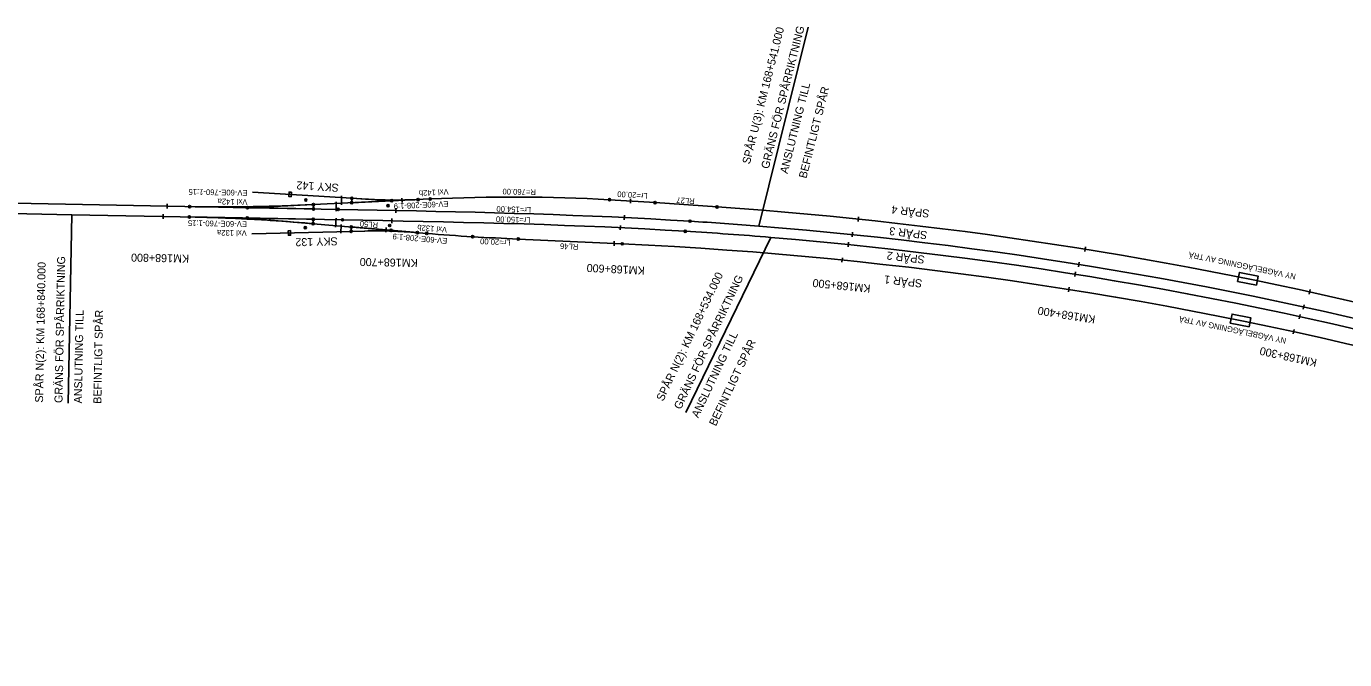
# Model space of a CAD drawing. Extents: x 185262 to 188870, y 6548921 to 6550022.
# Drawn here: x 186420 to 186997, y 6549712 to 6549989 of the extents above; entities that cross this region are included whole.
import ezdxf

# ---------------------------------------------------------------- set-up
doc = ezdxf.new("R2010")
doc.units = 0
for name, color, linetype in [('Befintligt spår som justeras', 7, 'Continuous'), ('BKS 1 verklig mangan P', 7, 'Continuous'), ('BKS 2 verklig mangan P', 7, 'Continuous'), ('FSK P', 7, 'Continuous'), ('Gräns för anslutning L', 7, 'Continuous'), ('Gräns för anslutning T', 7, 'Continuous'), ('Hinderpåle P', 7, 'Continuous'), ('Längdm markering (primär) L', 7, 'Continuous'), ('Längdmätning T', 7, 'Continuous'), ('MKP fiktiv P', 7, 'Continuous'), ('Ny Vägbeläggning L', 7, 'Continuous'), ('Ny Vägbeläggning T', 7, 'Continuous'), ('Spår bef projekterat behålls L', 7, 'Continuous'), ('Spår nr T', 7, 'Continuous'), ('Spårgeometri T', 7, 'Continuous'), ('Spårmitt projekterad L', 7, 'Continuous'), ('Spårmitt tp P', 7, 'Continuous'), ('Stoppbock P', 7, 'Continuous'), ('Växel linjevikt 2 L', 7, 'Continuous'), ('Växelnummer T', 7, 'Continuous'), ('Växeltyp T', 7, 'Continuous')]:
    doc.layers.add(name, color=color, linetype=linetype)

msp = doc.modelspace()

# ---------------------------------------------------------------- linework, layer by layer
at = {"layer": 'Befintligt spår som justeras'}
for p, q in [((186556.53, 6549908.61), (186401.75, 6549911.55)), ((186558.43, 6549904.05), (186440.01, 6549906.29))]:
    msp.add_line(p, q, dxfattribs=at)
for points in [[(186710.43, 6549903.46), (186701.89, 6549903.97), (186693.34, 6549904.45), (186684.8, 6549904.89), (186676.25, 6549905.29), (186667.71, 6549905.66), (186659.16, 6549906), (186650.61, 6549906.32), (186642.06, 6549906.6), (186633.51, 6549906.87), (186624.95, 6549907.12), (186616.4, 6549907.34), (186607.85, 6549907.55), (186599.3, 6549907.75), (186590.74, 6549907.94), (186582.19, 6549908.11), (186573.63, 6549908.28), (186565.08, 6549908.45), (186556.53, 6549908.61)], [(186708.34, 6549899.08), (186699.53, 6549899.6), (186690.72, 6549900.08), (186681.91, 6549900.52), (186673.09, 6549900.92), (186664.28, 6549901.29), (186655.46, 6549901.63), (186646.64, 6549901.94), (186637.82, 6549902.23), (186629, 6549902.49), (186620.18, 6549902.73), (186611.36, 6549902.95), (186602.54, 6549903.16), (186593.72, 6549903.35), (186584.9, 6549903.53), (186576.08, 6549903.71), (186567.25, 6549903.88), (186558.43, 6549904.05)]]:
    msp.add_lwpolyline(points, dxfattribs=at)
for centre, radius, start, end in [((186599.87, 6548133.91), 1773, 85.4491, 86.42498), ((186599.86, 6548133.91), 1768.5, 85.26658, 86.48344)]:
    msp.add_arc(centre, radius, start, end, dxfattribs=at)
at = {"layer": 'BKS 1 verklig mangan P'}
for centre in [(186562.49, 6549911.54), (186545.74, 6549908.81), (186545.65, 6549904.29), (186562.29, 6549900.93)]:
    msp.add_circle(centre, 0.5, dxfattribs=at)
at = {"layer": 'BKS 2 verklig mangan P'}
for centre in [(186545.71, 6549910.74), (186562.51, 6549913.47), (186545.55, 6549902.37), (186562.23, 6549899)]:
    msp.add_circle(centre, 0.5, dxfattribs=at)
at = {"layer": 'FSK P'}
for centre in [(186591.48, 6549912.92), (186491.45, 6549905.32), (186491.53, 6549909.84), (186591.2, 6549898.45)]:
    msp.add_circle(centre, 0.5, dxfattribs=at)
at = {"layer": 'Gräns för anslutning L'}
for p, q in [((186740.55, 6549901.32), (186762.12, 6549988.27)), ((186440.01, 6549906.29), (186438.45, 6549823.88)), ((186745.8, 6549896.38), (186708.64, 6549819.85))]:
    msp.add_line(p, q, dxfattribs=at)
at = {"layer": 'Hinderpåle P'}
for centre, radius in [((186542.39, 6549912.66), 0.5), ((186542.39, 6549912.66), 0.2), ((186578.39, 6549910.24), 0.5), ((186578.39, 6549910.24), 0.2), ((186542.16, 6549900.57), 0.5), ((186542.16, 6549900.57), 0.2), ((186579.07, 6549901.58), 0.5), ((186579.07, 6549901.58), 0.2)]:
    msp.add_circle(centre, radius, dxfattribs=at)
at = {"layer": 'Längdm markering (primär) L'}
for points in [[(186481.72, 6549909.03), (186481.76, 6549911.03)], [(186584.5, 6549911.58), (186584.4, 6549913.58)], [(186684.32, 6549911.3), (186684.45, 6549913.29)], [(186479.99, 6549904.54), (186480.03, 6549906.54)], [(186581.7, 6549907.12), (186581.74, 6549909.12)], [(186681.62, 6549904.04), (186681.72, 6549906.04)], [(186783.95, 6549903.36), (186784.16, 6549905.35)], [(186577.35, 6549898.64), (186577.52, 6549900.63)], [(186579.97, 6549902.63), (186580.01, 6549904.63)], [(186679.89, 6549899.62), (186679.99, 6549901.61)], [(186677.2, 6549892.72), (186677.3, 6549894.72)], [(186779.55, 6549892.26), (186779.76, 6549894.25)], [(186781.28, 6549896.6), (186781.48, 6549898.59)], [(186883.02, 6549890.23), (186883.34, 6549892.21)], [(186776.87, 6549885.49), (186777.08, 6549887.48)], [(186880.35, 6549883.57), (186880.67, 6549885.55)], [(186878.64, 6549879.29), (186878.95, 6549881.27)], [(186875.97, 6549872.63), (186876.29, 6549874.6)], [(186981.19, 6549871.56), (186981.62, 6549873.52)], [(186978.54, 6549864.98), (186978.97, 6549866.93)], [(186976.83, 6549860.75), (186977.26, 6549862.7)], [(186974.18, 6549854.16), (186974.61, 6549856.11)]]:
    msp.add_lwpolyline(points, dxfattribs=at)
at = {"layer": 'MKP fiktiv P'}
for centre in [(186579.95, 6549912.37), (186516.75, 6549904.84), (186516.83, 6549909.36), (186579.7, 6549899.44)]:
    msp.add_circle(centre, 0.5, dxfattribs=at)
at = {"layer": 'Ny Vägbeläggning L'}
for points in [[(186958.12, 6549875.45), (186949.89, 6549877.12), (186950.68, 6549881.04), (186958.92, 6549879.37)], [(186954.92, 6549857.22), (186946.69, 6549858.9), (186947.49, 6549862.82), (186955.72, 6549861.14)]]:
    msp.add_lwpolyline(points, close=True, dxfattribs=at)
at = {"layer": 'Spår bef projekterat behålls L'}
msp.add_line((186440.01, 6549906.29), (185262.41, 6549928.63), dxfattribs=at)
for centre, radius, start, end in [((186599.87, 6548133.91), 1773, 74.68797, 85.4491), ((186599.86, 6548133.91), 1768.5, 74.0572, 85.26658)]:
    msp.add_arc(centre, radius, start, end, dxfattribs=at)
at = {"layer": 'Spårmitt projekterad L'}
for p, q in [((186562.51, 6549913.47), (186519.07, 6549916.21)), ((186596.76, 6549913.17), (186545.71, 6549910.74)), ((186568.43, 6549913.1), (186562.51, 6549913.47)), ((186722.27, 6549909.7), (186695.16, 6549911.57)), ((186545.71, 6549910.74), (186542.11, 6549910.57)), ((186545.55, 6549902.37), (186541.96, 6549902.68)), ((186595.28, 6549898.1), (186545.55, 6549902.37)), ((186562.23, 6549899), (186518.72, 6549897.91)), ((186568.16, 6549899.15), (186562.23, 6549899)), ((186680.81, 6549893.55), (186635.28, 6549895.65))]:
    msp.add_line(p, q, dxfattribs=at)
for points in [[(186695.16, 6549911.57), (186692.67, 6549911.74), (186690.17, 6549911.91), (186687.68, 6549912.08), (186685.18, 6549912.24), (186682.69, 6549912.4), (186680.19, 6549912.56), (186677.7, 6549912.71), (186675.2, 6549912.85)], [(186635.28, 6549895.65), (186632.78, 6549895.76), (186630.28, 6549895.88), (186627.78, 6549896), (186625.29, 6549896.12), (186622.79, 6549896.24), (186620.29, 6549896.37), (186617.8, 6549896.51), (186615.3, 6549896.65)]]:
    msp.add_lwpolyline(points, dxfattribs=at)
for centre, radius, start, end in [((186581.56, 6550121.12), 208.44, 266.38717, 272.72736), ((186632.92, 6549154.03), 760, 86.81095, 92.72736), ((186477.03, 6549145.45), 760, 85.09921, 88.91329), ((186505.94, 6550669.71), 760, 268.91328, 272.72736), ((186599.87, 6548133.91), 1780, 65.67718, 86.05706), ((186573.4, 6549690.78), 208.44, 85.09921, 91.4394), ((186660.21, 6550655.33), 760, 265.09921, 266.61233), ((186599.86, 6548133.91), 1761.5, 63.60482, 87.36623)]:
    msp.add_arc(centre, radius, start, end, dxfattribs=at)
at = {"layer": 'Spårmitt tp P'}
for centre in [(186596.76, 6549913.17), (186675.2, 6549912.85), (186695.16, 6549911.57), (186556.53, 6549908.61), (186722.27, 6549909.7), (186558.43, 6549904.05), (186708.34, 6549899.08), (186710.43, 6549903.46), (186595.28, 6549898.1), (186615.3, 6549896.65), (186635.28, 6549895.65), (186680.81, 6549893.55)]:
    msp.add_circle(centre, 0.5, dxfattribs=at)
at = {"layer": 'Stoppbock P'}
for points in [[(186535.97, 6549914.14), (186536.1, 6549916.14), (186535.1, 6549916.2), (186534.97, 6549914.21)], [(186535.69, 6549899.33), (186535.74, 6549897.34), (186534.74, 6549897.31), (186534.69, 6549899.31)]]:
    msp.add_lwpolyline(points, close=True, dxfattribs=at)
at = {"layer": 'Växel linjevikt 2 L'}
for points in [[(186555.59, 6549911.93), (186555.65, 6549907.91)], [(186558.02, 6549914.47), (186557.99, 6549910.61)], [(186558.02, 6549914.47), (186557.99, 6549910.61)], [(186591.48, 6549912.92), (186579.95, 6549912.37)], [(186491.45, 6549905.32), (186516.75, 6549904.84)], [(186491.53, 6549909.84), (186516.83, 6549909.36)], [(186555.59, 6549904.82), (186555.38, 6549900.81)], [(186557.71, 6549898.17), (186557.83, 6549902.03)], [(186557.71, 6549898.17), (186557.83, 6549902.03)], [(186591.2, 6549898.45), (186579.7, 6549899.44)]]:
    msp.add_lwpolyline(points, dxfattribs=at)
for points in [[(186579.95, 6549912.37), (186562.49, 6549911.54), (186562.51, 6549913.47)], [(186591.48, 6549912.92), (186562.49, 6549911.54), (186562.51, 6549913.47), (186568.43, 6549913.1), (186568.43, 6549913.1), (186569.78, 6549913.02), (186571.14, 6549912.94), (186572.49, 6549912.88), (186573.85, 6549912.83), (186575.2, 6549912.78), (186576.56, 6549912.74), (186577.92, 6549912.71), (186579.27, 6549912.7), (186580.63, 6549912.68), (186581.99, 6549912.68), (186583.34, 6549912.69), (186584.7, 6549912.71), (186586.05, 6549912.73), (186587.41, 6549912.76), (186588.77, 6549912.81), (186590.12, 6549912.86)], [(186491.45, 6549905.32), (186545.65, 6549904.29), (186545.55, 6549902.37), (186541.96, 6549902.68), (186541.96, 6549902.68), (186539.44, 6549902.89), (186536.92, 6549903.09), (186534.39, 6549903.29), (186531.87, 6549903.47), (186529.35, 6549903.65), (186526.82, 6549903.82), (186524.3, 6549903.98), (186521.78, 6549904.14), (186519.25, 6549904.28), (186516.72, 6549904.42), (186514.2, 6549904.55), (186511.67, 6549904.67), (186509.14, 6549904.78), (186506.62, 6549904.88), (186504.09, 6549904.97), (186501.56, 6549905.06), (186499.03, 6549905.14), (186496.5, 6549905.21), (186493.97, 6549905.27)], [(186491.53, 6549909.84), (186545.74, 6549908.81), (186545.71, 6549910.74), (186542.11, 6549910.57), (186542.11, 6549910.57), (186539.58, 6549910.45), (186537.05, 6549910.34), (186534.53, 6549910.24), (186532, 6549910.15), (186529.47, 6549910.07), (186526.94, 6549910), (186524.41, 6549909.93), (186521.88, 6549909.87), (186519.35, 6549909.82), (186516.83, 6549909.78), (186514.3, 6549909.75), (186511.77, 6549909.73), (186509.24, 6549909.71), (186506.71, 6549909.71), (186504.18, 6549909.71), (186501.65, 6549909.72), (186499.12, 6549909.74), (186496.59, 6549909.76), (186494.06, 6549909.8)], [(186516.83, 6549909.36), (186545.74, 6549908.81), (186545.71, 6549910.74)], [(186516.75, 6549904.84), (186545.65, 6549904.29), (186545.55, 6549902.37)], [(186579.7, 6549899.44), (186562.29, 6549900.93), (186562.23, 6549899)], [(186591.2, 6549898.45), (186562.29, 6549900.93), (186562.23, 6549899), (186568.16, 6549899.15), (186568.16, 6549899.15), (186569.52, 6549899.18), (186570.87, 6549899.2), (186572.23, 6549899.21), (186573.59, 6549899.22), (186574.94, 6549899.21), (186576.3, 6549899.2), (186577.66, 6549899.17), (186579.01, 6549899.14), (186580.37, 6549899.1), (186581.73, 6549899.05), (186583.08, 6549898.99), (186584.44, 6549898.92), (186585.79, 6549898.85), (186587.15, 6549898.76), (186588.5, 6549898.67), (186589.85, 6549898.57)]]:
    msp.add_lwpolyline(points, close=True, dxfattribs=at)

# ---------------------------------------------------------------- texts
at = {"layer": 'Gräns för anslutning T'}
for s, rotation, p in [('SPÅR U(3): KM 168+541.000', 75.84713, (186736.57, 6549928.17)), ('GRÄNS FÖR SPÅRRIKTNING', 75.84713, (186744.82, 6549926.09)), ('ANSLUTNING TILL ', 75.84713, (186753.06, 6549924.01)), ('BEFINTLIGT SPÅR', 75.84713, (186761.3, 6549921.93)), ('SPÅR N(2): KM 168+840.000', 88.91329, (186427.45, 6549824.09)), ('GRÄNS FÖR SPÅRRIKTNING', 88.91329, (186435.95, 6549823.93)), ('SPÅR N(2): KM 168+534.000', 64.65656, (186698.67, 6549824.5)), ('GRÄNS FÖR SPÅRRIKTNING', 64.65656, (186706.35, 6549820.86)), ('ANSLUTNING TILL ', 88.91329, (186444.45, 6549823.77)), ('BEFINTLIGT SPÅR', 88.91329, (186452.95, 6549823.61)), ('ANSLUTNING TILL ', 64.65656, (186714.03, 6549817.23)), ('BEFINTLIGT SPÅR', 64.65656, (186721.72, 6549813.59))]:
    msp.add_text(s, height=3.5, rotation=rotation, dxfattribs=at).set_placement(p)
at = {"layer": 'Längdmätning T'}
for s, rotation, p in [('KM168+800', 178.91329, (186491.36, 6549888.82)), ('KM168+700', 178.86309, (186591.37, 6549886.9)), ('KM168+600', 177.31751, (186690.66, 6549883.59)), ('KM168+500', 174.16507, (186789.47, 6549875.66)), ('KM168+400', 170.92527, (186887.86, 6549862.12)), ('KM168+300', 167.68548, (186984.82, 6549843.14))]:
    msp.add_text(s, height=3.5, rotation=rotation, dxfattribs=at).set_placement(p)
at = {"layer": 'Ny Vägbeläggning T'}
for p in [(186975.54, 6549880.37), (186971.34, 6549852.32)]:
    msp.add_text('NY VÄGBELÄGGNING AV TRÄ', height=2.5, rotation=168.21567, dxfattribs=at).set_placement(p)
at = {"layer": 'Spår nr T'}
for s, rotation, p in [('SKY 142', 176.38717, (186556.88, 6549919.75)), ('SPÅR 4', 173.34743, (186815.27, 6549908.42)), ('SPÅR 3', 173.31516, (186814.34, 6549899)), ('SKY 132', 181.4394, (186556.26, 6549896.43)), ('SPÅR 2', 173.45469, (186813.2, 6549888.31)), ('SPÅR 1', 173.41767, (186812.11, 6549877.88))]:
    msp.add_text(s, height=3.5, rotation=rotation, dxfattribs=at).set_placement(p)
at = {"layer": 'Spårgeometri T'}
for s, rotation, p in [('R=760.00', 178.91329, (186643.02, 6549917.4)), ('Lr=20.00', 176.24553, (186691.95, 6549915.7)), ('RL27', 176.05706, (186712.53, 6549913.38)), ('Lr=150.00', 178.30583, (186640.73, 6549905.15)), ('Lr=154.00', 178.29121, (186640.94, 6549909.65)), ('RL50', 175.09921, (186574.06, 6549902.94)), ('Lr=20.00', 177.17775, (186631.95, 6549895.29)), ('RL46', 177.36623, (186661.61, 6549893.45))]:
    msp.add_text(s, height=2.5, rotation=rotation, dxfattribs=at).set_placement(p)
at = {"layer": 'Växelnummer T'}
for s, rotation, p in [('Vxl 142b', 182.72736, (186604.77, 6549917.54)), ('Vxl 142a', 178.91329, (186516.87, 6549913.06)), ('Vxl 132a', 178.91329, (186516.59, 6549899.42)), ('Vxl 132b', 175.09921, (186604.25, 6549900.85))]:
    msp.add_text(s, height=2.5, rotation=rotation, dxfattribs=at).set_placement(p)
at = {"layer": 'Växeltyp T'}
for s, rotation, p in [('EV-60E-760-1:15', 178.91329, (186516.95, 6549917.06)), ('EV-60E-208-1:9', 182.72736, (186604.73, 6549912.32)), ('EV-60E-760-1:15', 178.91329, (186516.67, 6549903.42)), ('EV-60E-208-1:9', 175.09921, (186604.35, 6549896.02))]:
    msp.add_text(s, height=2.5, rotation=rotation, dxfattribs=at).set_placement(p)

doc.saveas('drawing.dxf')
